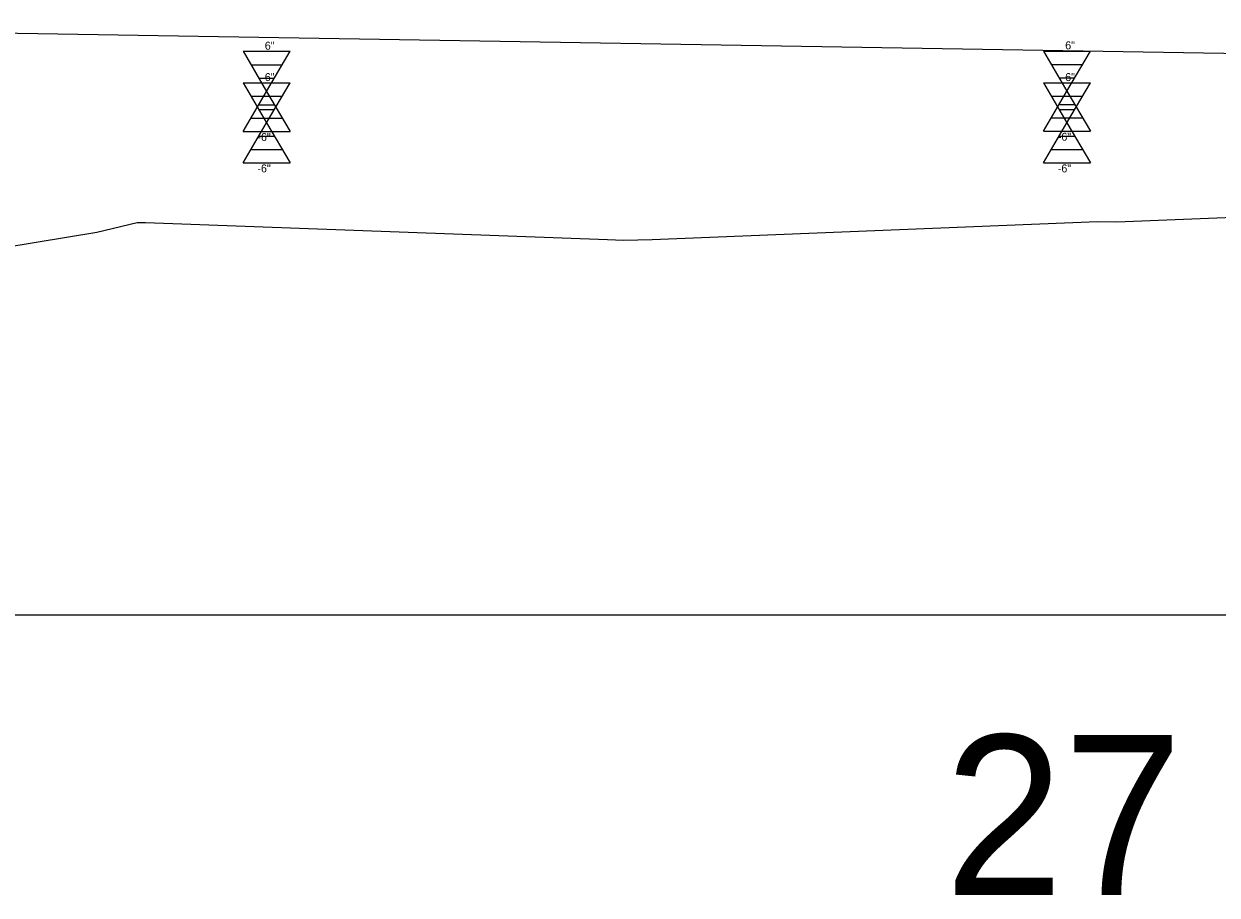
# Model space of a CAD drawing. Extents: x 573468 to 580768, y -57414 to -51768.
# Drawn here: x 575400.1 to 575474.6, y -53116 to -53061.6 of the extents above; entities that cross this region are included whole.
import ezdxf

# ---------------------------------------------------------------- set-up
doc = ezdxf.new("R2010")
doc.units = 0
for name, color, linetype in [('Exist Profile Cell', 7, 'Continuous'), ('Exist Vertical Profile Ground Line', 7, 'Continuous'), ('Exist Vertical Profile Horizontal Axis Label Major', 7, 'Continuous'), ('Pattern 2', 7, 'Continuous'), ('Prop Vertical Profile Grade', 7, 'Continuous'), ('Scratch_Level_0', 7, 'Continuous')]:
    doc.layers.add(name, color=color, linetype=linetype)

msp = doc.modelspace()

# ---------------------------------------------------------------- linework, layer by layer
at = {"layer": 'Exist Profile Cell'}
msp.add_line((573765.214, -53098.544), (577467.911, -53098.544), dxfattribs=at)
at = {"layer": 'Exist Vertical Profile Ground Line'}
msp.add_lwpolyline([(575383.373, -53078.127), (575404.609, -53074.624), (575407.123, -53074.03), (575407.639, -53074.037), (575436.502, -53075.083), (575437.51, -53075.12), (575439.301, -53075.097), (575467.13, -53073.968), (575468.334, -53073.981), (575485.999, -53073.271), (575489.425, -53072.371), (575508.269, -53072.837), (575516.25, -53073.855), (575517.968, -53073.841), (575522.346, -53073.849), (575545.535, -53074.336), (575547.838, -53074.437), (575552.641, -53074.536)], dxfattribs=at)
at = {"layer": 'Pattern 2'}
for p, q in [((575413.748, -53065.294), (575416.68, -53065.294)), ((575413.748, -53065.294), (575415.214, -53067.794)), ((575415.214, -53067.794), (575416.68, -53065.294)), ((575463.748, -53065.294), (575466.68, -53065.294)), ((575463.748, -53065.294), (575465.214, -53067.794)), ((575465.214, -53067.794), (575466.68, -53065.294)), ((575414.236, -53066.128), (575416.191, -53066.128)), ((575464.236, -53066.128), (575466.191, -53066.128)), ((575414.725, -53066.961), (575415.703, -53066.961)), ((575464.725, -53066.961), (575465.703, -53066.961)), ((575413.748, -53070.294), (575415.214, -53067.794)), ((575415.214, -53067.794), (575416.68, -53070.294)), ((575463.748, -53070.294), (575465.214, -53067.794)), ((575465.214, -53067.794), (575466.68, -53070.294)), ((575414.725, -53068.628), (575415.703, -53068.628)), ((575464.725, -53068.628), (575465.703, -53068.628)), ((575414.236, -53069.461), (575416.191, -53069.461)), ((575464.236, -53069.461), (575466.191, -53069.461)), ((575413.748, -53070.294), (575416.68, -53070.294)), ((575463.748, -53070.294), (575466.68, -53070.294))]:
    msp.add_line(p, q, dxfattribs=at)
at = {"layer": 'Prop Vertical Profile Grade'}
msp.add_line((575365.214, -53061.619), (575695.214, -53067.094), dxfattribs=at)
at = {"layer": 'Scratch_Level_0'}
for p, q in [((575413.748, -53063.334), (575416.68, -53063.334)), ((575413.748, -53063.334), (575415.214, -53065.834)), ((575415.214, -53065.834), (575416.68, -53063.334)), ((575463.748, -53063.314), (575466.68, -53063.314)), ((575463.748, -53063.314), (575465.214, -53065.814)), ((575465.214, -53065.814), (575466.68, -53063.314)), ((575414.236, -53064.168), (575416.191, -53064.168)), ((575464.236, -53064.148), (575466.191, -53064.148)), ((575414.725, -53065.001), (575415.703, -53065.001)), ((575464.725, -53064.981), (575465.703, -53064.981)), ((575413.748, -53068.334), (575415.214, -53065.834)), ((575415.214, -53065.834), (575416.68, -53068.334)), ((575463.748, -53068.314), (575465.214, -53065.814)), ((575465.214, -53065.814), (575466.68, -53068.314)), ((575414.725, -53066.668), (575415.703, -53066.668)), ((575464.725, -53066.648), (575465.703, -53066.648)), ((575414.236, -53067.501), (575416.191, -53067.501)), ((575464.236, -53067.481), (575466.191, -53067.481)), ((575413.748, -53068.334), (575416.68, -53068.334)), ((575463.748, -53068.314), (575466.68, -53068.314))]:
    msp.add_line(p, q, dxfattribs=at)

# ---------------------------------------------------------------- texts
at = {"layer": 'Exist Vertical Profile Horizontal Axis Label Major'}
msp.add_text('27', height=10, dxfattribs=at).set_placement((575457.556, -53116.044))
at = {"layer": 'Pattern 2'}
for s, p in [('6"', (575415.101, -53065.193)), ('6"', (575465.101, -53065.193)), ('-6"', (575414.64, -53070.897)), ('-6"', (575464.64, -53070.897))]:
    msp.add_text(s, height=0.5, rotation=360, dxfattribs=at).set_placement(p)
at = {"layer": 'Scratch_Level_0'}
for s, p in [('6"', (575415.101, -53063.233)), ('6"', (575465.101, -53063.213)), ('-6"', (575414.64, -53068.937)), ('-6"', (575464.64, -53068.917))]:
    msp.add_text(s, height=0.5, dxfattribs=at).set_placement(p)

doc.saveas('drawing.dxf')
